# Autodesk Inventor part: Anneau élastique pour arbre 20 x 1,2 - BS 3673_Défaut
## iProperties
Shininess: 64.0
Length Units: 11269
Angle Units: 11279
Time Units: 11290
Mass Units: 11283
Length Display Precision: 3
Angle Display Precision: 2
Compacted: True
Part Number: Anneau élastique pour arbre 20 x 1,2 - BS 3673_Défaut
Document SubType Name: Modeling
Created: 2006-01
Material: Par défaut
Designer: riri
Density: 0.0
Volumn: 0.0
Area: 0.0
PropertySet Name: Model Information
Control State: 0
Master: False
Checked Out: False
Author: riri
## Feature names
1. Base1
